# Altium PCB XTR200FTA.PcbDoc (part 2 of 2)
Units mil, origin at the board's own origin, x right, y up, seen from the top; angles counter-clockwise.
Board outline 3639.76 x 1623.7 mil, 4 copper layers (Top Layer, Layer 1, Layer 2, Bottom Layer), stack 53.912 mil thick; 93 components, 52 nets, 249 pads, 61 vias.
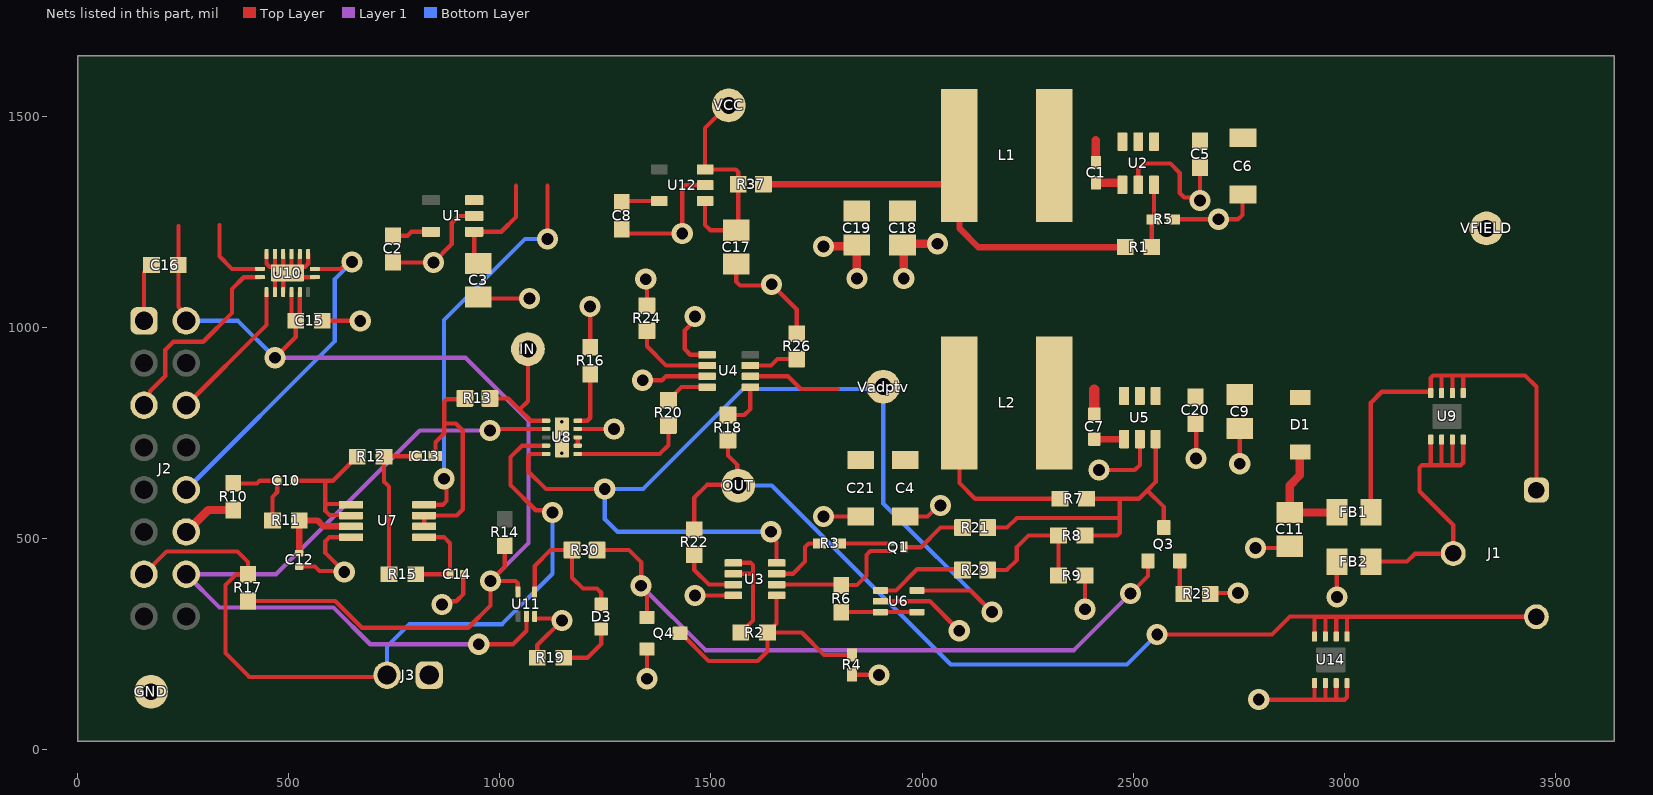
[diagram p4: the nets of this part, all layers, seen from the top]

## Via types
v1: diameter 50, hole 28, Top Layer to Bottom Layer, tented both sides, 48 vias
v2: diameter 19.68, hole 7.87, Top Layer to Bottom Layer, tented both sides, 13 vias

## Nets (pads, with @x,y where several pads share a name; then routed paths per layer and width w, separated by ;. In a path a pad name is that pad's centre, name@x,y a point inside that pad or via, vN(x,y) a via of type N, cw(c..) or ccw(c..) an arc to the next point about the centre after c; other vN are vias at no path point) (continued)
GND: C2.1 C3.1 C4.1 C5.2 C6.2 C8.1 C9.2 C11.2 C12.1 C14.1 C15.2 C16.2 C17.1 C18.2 C19.2 C20.2 C21.1 FB2.1 GND.1 J2.1 J3.1 Q4.2 R4.1 R5.1 R9.1 R16.1 R19.2 R23.1 R24.1 R26.1 U1.2 U2.2 U3.4 U4.1 U4.3 U5.2 U6.2 U7.4 U8.9 U8.11 U10.3 U10.4 U10.8 U10.10 U10.11 U10.12 U10.13 U10.14 U10.15 U10.17 U11.3 U12.2 U14.5 U14.6 U14.7 U14.8 | length 5210.6
  Top Layer w10: J2.1@157.48,1015.35 157.48,1130.52 174.21,1147.25 C16.2@175.2,1147.25 ; U10.15@447.79,1173.85 447.79,1150.68 455.21,1143.26 462.63,1143.26 462.63,1133.42 v2(467.47,1128.58) U10.3@467.47,1083.3 ; U10.17@467.47,1133.42 U10.14@467.47,1173.85 ; U10.4@487.16,1083.3 487.16,1118.73 U10.17@497,1128.58 ; U10.13@487.16,1173.85 487.16,1138.42 U10.17@497,1128.58 ; U10.12@506.84,1173.85 506.84,1138.42 U10.17@497,1128.58 ; C12.1@524.86,433.6 562.44,433.6 573.27,422.77 v1@629.86,422.77 ; U10.17@526.53,1123.58 531.37,1118.73 U10.8@561.96,1118.73 ; U10.17@526.53,1138.42 531.37,1143.26 538.79,1143.26 546.21,1150.68 U10.10@546.21,1173.85 ; U10.17@526.53,1143.26 U10.11@526.53,1173.85 ; C15.2@579.85,1015.35 v1(669.61,1015.35) ; v1(631.69,420.95) v1@629.86,422.77 ; U7.4@647.7,503.05 596.58,503.05 586.94,493.41 586.94,465.69 v1@629.86,422.77 ; C2.1@747.1,1153.99 747.3,1153.79 v1(842.87,1153.79) 886.14,1197.06 886.14,1247.03 902.73,1263.63 U1.2@939.29,1263.63 ; v1(863.29,343.79) 870.94,351.45 896.9,351.45 913.69,368.24 C14.1@913.69,415.35 ; C3.1@949.1,1071.48 952.41,1068.18 v1(1070.17,1068.18) ; U11.3@1082.68,315.35 1082.68,311.63 1083.58,310.73 1142.45,310.73 v1(1147.07,306.1) 1088.58,247.61 R19.2@1088.58,217.52 ; U8.9@1184.48,759.06 v1(1270.34,759.06) ; R16.1@1213.99,952.44 v1(1213.99,1049.35) ; C8.1@1288.59,1232.49 1299.15,1221.94 v1(1432.09,1221.94) 1432.09,1330.76 1437.94,1336.61 U12.2@1486.22,1336.61 ; v1(1338.39,874.76) 1384.19,874.76 1393.43,884 U4.3@1490.96,884 ; v1(1345.6,1113.99) 1348.43,1111.17 R24.1@1348.43,1051.09 ; v1(1348.43,167.91) Q4.2@1348.43,238.19 ; v1(1461.91,365.16) U3.4@1553.15,365.16 ; v1(1461.91,1025.37) 1461.91,1016.73 1437.94,992.76 1437.94,948.43 1451.2,935.18 U4.1@1490.96,935.18 ; C17.1@1559.78,1149.99 1559.78,1108.66 1569.19,1099.25 1641.24,1099.25 v1(1643.85,1101.86) 1703,1042.71 R26.1@1703,984.59 ; v1(1766.24,552.19) C21.1@1854.52,552.19 ; R4.1@1834.02,177 v1(1898.1,177) ; C19.2@1842.13,1191.78 C19.2@1845.76,1188.14 ; U6.2@1901.14,351.18 2018.41,351.18 v1(2088,281.59) ; C18.2@1953.7,1195.08 C18.2@1956.51,1192.28 ; C4.1@1960.65,552.19 2012.79,552.19 2038.68,578.08 v1(2043.46,578.08) ; v1(2385.99,332.29) R9.1@2385.99,412.26 ; v1(2419.04,662.1) 2503.69,662.1 2515.78,674.19 U5.2@2515.78,735.23 ; U2.2@2511.93,1337.36 2511.93,1374.57 2525.15,1387.8 2587.9,1387.8 2610.37,1365.33 2610.37,1318.14 2620.84,1307.67 2650.81,1307.67 v1(2658.46,1300.02) C5.2@2658.46,1378.38 ; R5.1@2594.49,1255.88 v1(2701.69,1255.88) 2748.23,1255.88 2758.54,1266.19 2758.54,1313.33 C6.2@2759.96,1314.75 ; C20.2@2647.42,772 2649.05,770.38 v1(2649.05,689.11) ; R23.1@2682.31,368.66 2684.49,370.85 v1(2748.23,370.85) ; v1(2752.33,676.99) C9.2@2752.33,760.53 ; v1(2789.73,477.36) 2866.93,477.36 C11.2@2871.06,481.49 ; v1(2797.36,118.41) 2797.66,118.11 2929.19,118.11 ; U14.5@2929.49,157.48 2929.49,118.41 2929.19,118.11 ; U14.6@2955.08,157.48 2955.08,118.11 ; U14.7@2980.67,157.48 2980.67,121.04 2977.74,118.11 ; v1(2982.23,361.29) 2982.23,444.73 FB2.1@2982.73,445.23 ; U14.8@3006.26,157.48 3006.26,123.97 3000.4,118.11 2977.74,118.11 ; 2929.19,118.11 2955.08,118.11 ; 2955.08,118.11 2977.74,118.11
  Top Layer w20: v1(1766.94,1191.78) C19.2@1842.13,1191.78 ; v1(1845.76,1115.7) C19.2@1845.76,1188.14 ; v1(1956.51,1115.29) C18.2@1956.51,1192.28 ; C18.2@1956.51,1197.89 v1(2036.29,1197.89)
  other v2: 1147.07,701.97 1147.07,739.37 1147.07,776.77 526.53,1128.58
ID0: J2.5 U10.1 | length 480.9
  Top Layer w10: J2.5@157.48,815.35 157.48,830.23 171.48,844.22 171.48,848.51 207.88,884.91 207.88,946.59 227.26,965.97 297.86,965.97 365.55,1033.66 365.55,1090.6 393.68,1118.73 U10.1@432.04,1118.73
LDO_IN: C17.2 R37.2 U12.1 U12.3 VCC.1 | length 532.5
  Top Layer w10: U12.1@1486.22,1299.21 1486.22,1242.42 1498.66,1229.99 C17.2@1559.78,1229.99 1564.76,1234.98 R37.2@1564.76,1338.58 1564.76,1368.03 1558.78,1374.02 U12.3@1486.22,1374.02 1486.22,1471.64 1540.17,1525.59 VCC.1@1542.14,1525.59
MODE: J2.14 U8.2 U11.2 | length 1916
  Top Layer w10: v1(950.13,249.44) 1031.07,249.44 1062.99,281.36 U11.2@1062.99,315.35 ; v1(976.86,755.51) 980.4,759.06 U8.2@1109.67,759.06
  Layer 1 w10: v1(950.13,249.44) 693.4,249.44 606.22,336.62 336.22,336.62 J2.14@257.48,415.35 470.2,415.35 810.36,755.51 v1(976.86,755.51)
MODE_CTRL: Q3.1 Q4.1 R30.1 | length 1627
  Top Layer w10: R30.1@1230.51,472.44 1306.22,472.44 1334.77,443.9 1334.77,388.26 v1(1334.66,388.15) 1334.66,377.33 1348.43,363.56 Q4.1@1348.43,312.99 Q4.1@1347.07,311.63 ; v1(2493.89,369.7) 2535.24,411.05 Q3.1@2535.17,446.94 Q3.1@2535.17,446.94
  Layer 1 w10: v1@1334.77,388.15 1487.4,235.52 2359.71,235.52 v1(2493.89,369.7)
NetC1_1: C1.1 L1.2 U2.6 | length 53
  Top Layer w20: C1.1@2411.61,1389.76 2411.61,1442.78
NetC1_2: C1.2 U2.1 | length 67
  Top Layer w20: C1.2@2411.61,1342.52 2472.72,1342.52 2474.53,1340.71 U2.1@2474.53,1337.36
NetC7_1: C7.1 U5.1 | length 70.2
  Top Layer w15: C7.1@2408.2,735.16 C7.1@2408.2,735.16 2478.34,735.19 U5.1@2478.38,735.23
NetC7_2: C7.2 L2.2 U5.6 | length 57.8
  Top Layer w25: C7.2@2408.2,794.21 2408.2,852.01
NetC10_1: C10.1 R10.2 R11.1 | length 206.3
  Top Layer w10: R10.2@369.01,630.45 425.02,630.45 431.38,636.81 C10.1@473.68,636.81 472.78,635.91 472.78,609.41 461.87,598.51 R11.1@461.87,542.72
NetC10_2: C10.2 R12.2 U7.1 U7.2 | length 371.6
  Top Layer w10: C10.2@513.05,636.81 586.94,636.81 ; U7.2@647.7,554.23 646.42,555.51 596.58,555.51 586.94,565.15 586.94,581.36 ; U7.1@647.7,579.82 646.16,581.36 586.94,581.36 ; R12.2@662.83,693.49 661.84,693.49 605.17,636.81 586.94,636.81 ; 586.94,581.36 586.94,636.81
NetC11_1: C11.1 D1.2 FB1.1 | length 265.1
  Top Layer w20: D1.2@2895.73,704.58 2894.23,703.08 2894.23,649.17 2871.06,626.01 C11.1@2871.06,561.49 2982.44,561.49 FB1.1@2982.73,561.77
NetC12_2: C12.2 R11.2 U7.3 | length 206.3
  Top Layer w15: C12.2@524.86,465.1 R11.2@524.86,542.72 568.28,542.72 582.35,528.64 U7.3@647.7,528.64
NetC13_1: C13.1 R13.2 U7.6 U7.7 | length 550.3
  Top Layer w10: U7.6@820.92,528.64 U7.7@820.92,554.23 897.94,554.23 912.21,568.5 912.21,755.51 895.73,772 868.45,772 ; C13.1@847.45,694.88 847.45,727.7 868.45,748.7 868.45,772 ; R13.2@917.41,831.75 915.44,829.78 874.31,829.78 868.45,823.93 868.45,772
NetC13_2: C13.2 R12.1 R15.1 | length 358
  Top Layer w10: R15.1@737.71,415.35 737.71,622.66 725.82,634.55 R12.1@725.82,693.49 727.21,694.88 C13.2@800.21,694.88
NetC14_2: C14.2 R15.2 U7.5 | length 222.1
  Top Layer w10: R15.2@800.7,415.35 C14.2@882.2,415.35 882.2,488.75 867.9,503.05 U7.5@820.92,503.05
NetC18_1: C18.1 C19.1 L1.1 R1.2 R37.1 | length 1096.1
  Top Layer w15: R37.1@1624.21,1338.58 2052.75,1338.58 2088.55,1374.39 L1.1@2088.55,1407.48 2088.55,1234.67 2133.23,1189.99 R1.2@2481.09,1189.99
NetD3_1: D3.1 R19.1 | length 137.2
  Top Layer w10: R19.1@1151.57,217.52 1207.3,217.52 1240.16,250.38 D3.1@1240.16,285.43
NetD3_2: D3.2 R30.2 U11.4 | length 338.6
  Top Layer w10: U11.4@1082.68,373.62 1082.68,435.04 1120.08,472.44 1165.87,472.44 1171.06,467.24 1171.06,406.92 1196.77,381.22 1230.51,381.22 1240.16,371.57 D3.2@1240.16,344.49
NetFB1_2: FB1.2 J1.1 U9.1 U9.2 U9.3 U9.4 | length 1084.7
  Top Layer w10: FB1.2@3062.73,561.77 3062.73,821.36 3088.73,847.36 3203.61,847.36 3204.71,846.26 U9.4@3204.71,844.41 3204.71,880.26 3210.57,886.12 3230.3,886.12 ; U9.3@3230.3,844.41 3230.3,886.12 ; U9.2@3255.89,844.41 3255.89,886.12 ; U9.1@3281.48,844.41 3281.48,884.15 3279.52,886.12 ; J1.1@3454.72,614.57 3454.72,859.18 3427.78,886.12 3279.52,886.12 ; 3230.3,886.12 3255.89,886.12 ; 3255.89,886.12 3279.52,886.12
NetFB2_2: FB2.2 J1.2 U9.5 U9.6 U9.7 U9.8 | length 785.1
  Top Layer w10: FB2.2@3062.73,445.23 3148.61,445.23 3167.31,463.93 3257.24,463.93 J1.2@3257.87,464.57 3257.87,532.18 3178.14,611.91 3178.14,667.7 3183.99,673.55 3202.74,673.55 ; U9.5@3204.71,734.17 3204.71,675.52 3202.74,673.55 ; U9.6@3230.3,734.17 3230.3,673.55 ; U9.7@3255.89,734.17 3255.89,674.06 3256.4,673.55 ; U9.8@3281.48,734.17 3281.48,679.41 3275.63,673.55 3256.4,673.55 ; 3202.74,673.55 3230.3,673.55 ; 3230.3,673.55 3256.4,673.55
NetQ1_1: Q1.1 R3.2 | length 122.4
  Top Layer w10: R3.2@1804.54,488.23 Q1.1@1926.89,488.23
NetQ1_2: Q1.2 R6.2 U3.6 | length 337.9
  Top Layer w10: U3.6@1655.51,390.75 1806.54,390.75 R6.2@1808.71,388.58 1809.89,389.76 1846.01,389.76 1868.14,411.89 1868.14,461.16 1877.45,470.47 Q1.2@1929.76,470.47
NetQ1_3: Q1.3 R21.1 | length 157.9
  Top Layer w10: Q1.3@1957.32,479.33 1997.16,479.33 2043.51,525.68 R21.1@2096.03,525.68
NetQ3_2: Q3.2 R23.2 | length 82.1
  Top Layer w10: Q3.2@2609.97,446.94 2609.97,378 R23.2@2619.32,368.66
NetQ4_3: Q4.3 R2.2 R4.2 U3.5 | length 606.1
  Top Layer w10: Q4.3@1427.17,275.59 1429.13,275.59 1494.65,210.08 1611.02,210.08 1633.86,232.92 R2.2@1633.86,277.11 1715.14,277.11 1768.01,224.25 R4.2@1834.02,224.25 ; R2.2@1634.84,277.11 1648.54,290.81 1648.54,291.79 1655.51,298.76 U3.5@1655.51,365.16
NetR1_1: R1.1 R5.2 U2.3 | length 149.5
  Top Layer w10: R1.1@2544.09,1189.99 2544.09,1252.72 2549.33,1257.97 U2.3@2549.33,1337.36
NetR2_1: R2.1 U3.1 U3.2 | length 268.2
  Top Layer w10: U3.2@1553.15,416.34 1599.78,416.34 ; U3.1@1553.15,441.93 1553.84,442.62 1593.92,442.62 1599.78,436.76 1599.78,416.34 ; R2.1@1570.87,277.11 1571.85,277.11 1585.55,290.81 1585.55,291.79 1599.78,306.02 1599.78,416.34
NetR3_1: R3.1 U3.7 | length 151.6
  Top Layer w10: U3.7@1655.51,416.34 1694.06,416.34 1722.96,445.25 1722.96,479.49 1731.7,488.23 R3.1@1757.29,488.23
NetR6_1: R6.1 U6.3 U6.4 | length 179.1
  Top Layer w10: R6.1@1808.71,325.59 U6.3@1901.14,325.59 U6.4@1987.76,325.59
NetR8_1: R8.1 R9.2 R29.2 | length 313.7
  Top Layer w10: R29.2@2155.48,425.29 2200.39,425.29 2224.41,449.31 2224.41,479.46 2251.87,506.93 R8.1@2323,506.93 R9.2@2323,412.26
NetR16_2: R16.2 U8.10 | length 136.5
  Top Layer w10: U8.10@1184.48,778.74 1207.24,778.74 1214.33,785.83 1214.33,889.12 R16.2@1213.99,889.45
NetR18_2: R18.2 U4.5 | length 111.1
  Top Layer w10: R18.2@1540.17,792.35 1578.77,792.35 1578.96,792.15 1593.32,806.52 U4.5@1593.32,858.41
NetR20_1: R20.1 U4.4 | length 104.6
  Top Layer w10: R20.1@1399.27,827.27 1430.41,858.41 U4.4@1490.96,858.41
NetR20_2: R20.2 U8.6 | length 270.5
  Top Layer w10: U8.6@1184.48,700 1378.6,700 1399.27,720.67 R20.2@1399.27,767.82
NetR22_1: R22.1 U3.3 | length 142.8
  Top Layer w10: R22.1@1460.63,461.31 1460.63,425.29 1495.17,390.75 U3.3@1553.15,390.75
NetR24_2: R24.2 U4.2 | length 197.9
  Top Layer w10: R24.2@1348.43,991.64 1348.43,955.14 1393.98,909.59 U4.2@1490.96,909.59
NetR26_2: R26.2 U4.7 | length 116.1
  Top Layer w10: U4.7@1593.32,909.59 1642.35,909.59 1657.91,925.14 R26.2@1703,925.14
NetR29_1: R29.1 U6.1 | length 216.6
  Top Layer w10: U6.1@1901.14,376.77 1938.19,376.77 1988.68,427.25 2094.06,427.25 R29.1@2096.03,425.29
NetU8_7: U8.7 U8.8 | length 19.7
  Top Layer w10: U8.7@1184.48,719.69 U8.8@1184.48,739.37
OD: J2.13 J3.2 R17.1 U8.4 | length 1904.7
  Top Layer w10: J2.13@157.48,415.35 211.16,469.03 379.04,469.03 403.5,444.57 R17.1@403.5,415.04 375.59,415.04 350.31,389.76 350.31,228.81 406.89,172.23 728.97,172.23 J3.2@732.99,176.25 ; U8.4@1109.67,719.69 1052.36,719.69 1025.59,692.91 1025.59,626.23 1085.15,566.66 1119.91,566.66 v1(1125.15,561.42)
  Bottom Layer w10: J3.2@732.99,176.25 732.99,243.85 786.24,297.1 1005.68,297.1 1125.15,416.57 v1(1125.15,561.42)
OUT: J1.3 OUT.1 R18.1 R22.2 U14.1 U14.2 U14.3 U14.4 | length 2610.4
  Top Layer w10: R22.2@1460.63,520.76 1460.63,596.66 1490.96,627 OUT.1@1562.54,627 ; R18.1@1540.17,732.9 1540.17,696.61 1562.54,674.25 OUT.1@1562.54,627 ; OUT.1@1564.42,625.11 OUT.1@1562.54,627 ; v1(2556.74,272.5) 2828.64,272.5 2871.06,314.93 2927.52,314.93 ; U14.4@2929.49,267.72 2929.49,312.96 2927.52,314.93 ; U14.3@2955.08,267.72 2955.08,314.76 ; U14.2@2980.67,267.72 2980.67,314.76 ; U14.1@3006.26,267.72 3006.26,314.76 ; J1.3@3454.72,314.57 3454.53,314.76 3006.26,314.76 ; 2927.52,314.93 2935.23,314.93 2935.39,314.76 2955.08,314.76 ; 2955.08,314.76 2980.67,314.76 ; 2980.67,314.76 3006.26,314.76
  Bottom Layer w10: OUT.1@1564.42,625.11 1644.04,625.11 2067.79,201.36 2485.59,201.36 v1(2556.74,272.5)
PWM_Input: J2.12 R10.1 | length 133.1
  Top Layer w20: J2.12@257.48,515.35 309.59,567.46 R10.1@369.01,567.46
SCLK: J2.6 U10.2 | length 346.8
  Top Layer w10: J2.6@257.48,815.35 447.79,1005.66 U10.2@447.79,1083.3
SDO: J2.10 U10.9 | length 796.4
  Top Layer w10: U10.9@561.96,1138.42 622.51,1138.42 638.88,1154.79 v1(649.7,1154.79)
  Bottom Layer w10: J2.10@257.48,615.35 609.37,967.25 609.37,1114.46 v1(649.7,1154.79)
Vbuck_out: C4.2 C21.2 L2.1 R7.2 U3.8 U4.6 U6.5 U8.5 Vadptv.1 | length 3201.8
  Top Layer w10: U8.5@1109.67,700 1073.28,700 1067.42,694.14 1067.42,658.59 1109.12,616.89 v1(1248.69,616.89) ; U4.6@1593.32,884 1682.24,884 1712.6,853.64 1800.55,853.64 ; v1(1642.35,515.84) 1642.35,505.01 1655.51,491.86 U3.8@1655.51,441.93 ; U6.5@1987.76,376.77 2114.17,376.77 v1(2165.35,325.59) ; L2.1@2088.55,929.32 L2.1@2088.55,821.05 2088.55,631.13 2125.75,593.93 R7.2@2326.52,593.93
  Bottom Layer w10: v1(1642.35,515.84) 1278.52,515.84 1248.69,545.67 v1(1248.69,616.89) 1339.56,616.89 1576.31,853.64 1908.15,853.64 1908.15,582.79 v1(2165.35,325.59) ; Vadptv.1@1908.15,859.46 Vadptv.1@1911.06,856.55
VDD-3V3: C2.2 C15.1 C16.1 J2.2 R14.2 R17.2 U1.5 U10.5 U10.6 U10.16 U11.5 | length 2936.2
  Top Layer w10: C16.1@238.19,1147.25 239.17,1148.23 239.17,1240.16 ; C16.1@239.17,1147.25 239.17,1048.53 J2.2@257.48,1030.23 ; 336.22,1242.34 336.22,1168.34 366.14,1138.42 U10.16@432.04,1138.42 ; R17.2@403.5,352.05 610.46,352.05 674.01,288.51 925.25,288.51 978.18,341.44 v1(978.18,399.1) ; v1(467.47,927.95) 516.85,977.33 C15.1@516.85,1015.35 ; U10.5@506.84,1083.3 506.84,1025.37 C15.1@516.85,1015.35 ; U10.6@526.53,1083.3 526.53,1025.03 C15.1@516.85,1015.35 ; C2.2@747.1,1216.98 781.64,1216.98 790.89,1226.23 U1.5@836.92,1226.23 ; R14.2@1011.86,482.68 1011.86,432.79 v1(978.18,399.1) ; U11.5@1043.31,373.62 1042.4,374.53 1042.4,394.13 1037.43,399.1 v1(978.18,399.1)
  Layer 1 w10: v1(467.47,927.95) 918.66,927.95 1067.91,778.7 1067.91,488.84 v1(978.18,399.1)
  Bottom Layer w10: J2.2@257.48,1015.35 380.07,1015.35 v1(467.47,927.95)
VDD-5V: C3.2 C8.2 U1.1 U1.3 U7.8 U12.5 | length 1304.3
  Top Layer w10: U7.8@820.92,579.82 865.14,579.82 874.12,588.8 874.12,635.22 v1(867.9,641.44) ; C3.2@949.1,1151.48 939.29,1161.3 U1.1@939.29,1226.23 1003.34,1226.23 1038.68,1261.56 1038.68,1335.18 ; v1(1112.95,1209.01) 1112.95,1335.18 ; C8.2@1282.68,1301.39 C8.2@1288.59,1295.49 1292.32,1299.21 U12.5@1377.95,1299.21
  Bottom Layer w10: v1(867.9,641.44) 867.9,1017.17 1059.74,1209.01 v1(1112.95,1209.01)
Vfb: Q3.3 R7.1 R8.2 R21.2 U5.3 | length 874
  Top Layer w10: R21.2@2155.48,525.68 2201.45,525.68 2224.41,548.64 2468.18,548.64 ; R8.2@2385.99,506.93 2462.32,506.93 2468.18,512.79 2468.18,548.64 ; R7.1@2389.51,593.93 2468.18,593.93 ; U5.3@2553.19,735.23 2553.19,633.55 2533.37,613.74 ; Q3.3@2572.57,525.68 2572.57,574.54 2533.37,613.74 ; 2468.18,548.64 2468.18,593.93 ; 2468.18,593.93 2513.56,593.93 2533.37,613.74
Vfield: C5.1 C6.1 C9.1 C20.1 D1.1 U2.4 U2.5 U5.4 U5.5 VFIELD.1
XTR_IN: IN.1 R13.1 U8.1 | length 306.1
  Top Layer w10: R13.1@976.86,831.75 1020.57,831.75 1047.07,805.25 ; IN.1@1066.69,948.43 1066.69,824.86 1047.07,805.25 ; U8.1@1109.67,778.74 1073.58,778.74 1047.07,805.25
pads on no net: J2.3 J2.4 J2.7 J2.8 J2.9 J2.11 J2.15 LBL1.0 U1.4 U4.8 U9.9 U10.7 U11.1 U12.4 U14.9
copper on no net:
  other v2: 2967.87,192.91 2943.27,212.6 2992.48,212.6 2967.87,232.28 3243.1,769.6 3218.49,789.29 3267.7,789.29 3243.1,808.97

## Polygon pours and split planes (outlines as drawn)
NetC18_1 on Top Layer "TOP_LAYER_NETC18_1_P005" (solid, pour order 5): 1787.59,1564.95 1787.59,1249.95 2131.23,1249.95 2131.23,1564.95
Vfield on Top Layer "TOP_LAYER_VFIELD_P017" (solid, pour order 17): 2503.58,1088.85 2503.58,815.67 2949.36,815.67 2955.26,821.57 2955.26,1088.85
VDD-3V3 on Top Layer "TOP_LAYER_VDD-3V3_P016" (solid, pour order 16): 767.11,1200.69 765.8,1202.01 765.8,1643.7 25.54,1643.7 25.54,1198.82
VDD-5V on Top Layer "TOP_LAYER_VDD-5V_P015" (solid, pour order 15): 1307.29,1290.11 918.61,1290.11 918.61,1643.7 1307.29,1643.7
Vbuck_out on Top Layer "TOP_LAYER_VBUCK_OUT_P011" (solid, pour order 11): 2133.57,978.58 2133.51,978.52 1787.59,978.52 1787.59,663.58 2133.43,663.58
Vfield on Top Layer "TOP_LAYER_VFIELD_P010" (solid, pour order 10): 2503.58,918.81 2503.58,1088.85 3639.75,1088.85 3639.75,917.62 2504.77,917.62
Vfield on Top Layer "TOP_LAYER_VFIELD_P013" (solid, pour order 13): 2952.76,1566.62 2952.76,917.62 3639.75,917.62 3639.75,1565.97
NetC7_2 on Top Layer "TOP_LAYER_NETC7_2_P012" (solid, pour order 12): 2489.76,813.65 2489.76,978.52 2301.97,978.52 2301.97,814.97
Vfield on Top Layer "TOP_LAYER_VFIELD_P009" (solid, pour order 9): 2503.58,1422.99 2503.58,1566.29 3639.75,1566.29 3639.75,1422.99
NetC1_1 on Top Layer "TOP_LAYER_NETC1_1_P008" (solid, pour order 8): 2486.22,1419.29 2486.22,1564.95 2268.09,1564.95 2268.09,1419.29
GND on Layer 2 "LAYER_2_GND_P000" (solid, pour order 0): -0.01,1643.7 -0.01,1407.11 -0.01,20 3639.75,20 3639.75,1643.7

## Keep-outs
Keep-Out Layer:
  text ".Layer_Name" at 577,-858.49 h60

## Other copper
Top Layer:
  text ".Layer_Name" at 577,-858.49 h60
Bottom Layer:
  text ".Layer_Name" at 577,-858.49 h60

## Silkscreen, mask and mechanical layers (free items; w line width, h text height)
Top Overlay:
  text "FT-EVP-XTR200-A" at 98.43,1482.28 h108.27
  text ".Layer_Name" at 577,-858.49 h23.62
Bottom Overlay:
  text ".Layer_Name" at 577,-858.49 h60
Top Paste:
  text ".Layer_Name" at 577,-858.49 h60
Bottom Paste:
  text ".Layer_Name" at 577,-858.49 h60
Top Solder:
  text ".Layer_Name" at 577,-858.49 h60
  text ".Layer_Name" at 577,-858.49 h60
Bottom Solder:
  text ".Layer_Name" at 577,-858.49 h60
Drill Guide:
  text ".Layer_Name" at 577,-858.49 h60
M1 Board Outline:
  lines w10: -0.01,20 0,1643.7 3641.91,1643.7 3641.54,19.7 -0.01,20
  text ".Layer_Name" at 577,-858.49 h60
M2 Board Dimensions:
  rectangle: 0,-275 125,-150
  rectangle: 125,-400 500,-275
  lines w7: 0,-275 1000,-275 ; 125,-400 125,-150 ; 250,-400 250,-150 ; 500,-400 500,-150 ; 750,-400 750,-150 ; 0,-400 1000,-400 1000,-150 0,-150 0,-400
  text ".Layer_Name" at 577,-858.49 h60
M3 3D STEP Top:
  text ".Layer_Name" at 577,-858.49 h60
M4 3D STEP Bottom:
  text ".Layer_Name" at 577,-858.49 h60
M5 Assembly Top:
  lines w10: -292,-930.17 6308,-930.17 ; -292,-726.83 6310,-726.83 ; -292,-523.5 -292,-1133.5 3713,-1133.5 6310,-1133.5 6310,-523.5 -291.5,-523.5 -291.5,-1133.5 1284,-1133.5 ; 2173,-1133.5 2173,-523.5 ; 3440,-726.83 3440,-523.5 ; 4280,-726.83 4280,-523.5 ; 4902,-1140 4902,-937.17
  text "COMPONENTS MARKED 'DNP' SHOULD NOT BE POPULATED." at 1153.5,-318.5 h60
  text "ASSEMBLY VARIANT:" at 1153,-434 h60
  text ".VariantName" at 2189,-434 h60
  text "PCB VIEWED FROM TOP SIDE" at -228.5,-655.67 h60
  text "BOARD #:" at 2248,-655.67 h60
  text ".PRJ_Number" at 2793.5,-655.67 h60
  text "REV:" at 3638,-655.67 h60
  text ".PCB_Rev" at 3929.5,-655.67 h60
  text "SVN REV:" at 4476,-655.67 h60
  text ".VersionControl_RevNumber" at 4982,-655.67 h60
  text "TID #:" at 2248,-859 h60
  text ".TID" at 2793.5,-859 h60
  text "PLOT NAME =" at -228.5,-1064.34 h60
  text ".plot_File_Name" at 577,-1064.34 h60
  text "GENERATED    :" at 2250,-1064.34 h60
  text ".Print_Date" at 3119.5,-1064.34 h60
  text ".Print_Time" at 3848.5,-1064.34 h60
  text "TEXAS INSTRUMENTS" at 5113,-1064.34 h60
M6 Assembly Bottom:
  lines w10: -292.5,-727.33 6309.5,-727.33 ; -290.5,-930.67 6309.5,-930.67 ; 1115.5,-1140.5 1115.5,-937.67 ; 1737.5,-727.33 1737.5,-524 ; 2577.5,-727.33 2577.5,-524 ; 3844.5,-1134 3844.5,-524 ; 4733.5,-1134 6309,-1134 6309,-524 -292.5,-524 -292.5,-1134 2304.5,-1134 6309.5,-1134 6309.5,-524
  text "COMPONENTS MARKED 'DNP' SHOULD NOT BE POPULATED." at 6102,-318 h60
  text ".VariantName" at 5058,-434 h60
  text "ASSEMBLY VARIANT:" at 6097,-434 h60
  text ".VersionControl_RevNumber" at 1035.5,-656.17 h60
  text "SVN REV:" at 1541.5,-656.17 h60
  text ".PCB_Rev" at 2088,-656.17 h60
  text "REV:" at 2379.5,-656.17 h60
  text ".PRJ_Number" at 3224,-656.17 h60
  text "BOARD #:" at 3769.5,-656.17 h60
  text "PCB VIEWED FROM BOTTOM SIDE" at 6246,-656.17 h60
  text ".TID" at 3224,-859.5 h60
  text "TID #:" at 3769.5,-859.5 h60
  text "TEXAS INSTRUMENTS" at 904.5,-1064.84 h60
  text ".Print_Time" at 2169,-1064.84 h60
  text ".Print_Date" at 2898,-1064.84 h60
  text "GENERATED    :" at 3767.5,-1064.84 h60
  text ".plot_File_Name" at 5440.5,-1064.84 h60
  text "PLOT NAME =" at 6246,-1064.84 h60
M9 Title Sheet:
  drawing of 57 lines, arcs and shapes, not listed
  text "1" at 739.84,8036.5 h70
  text "2" at 3235.5,8036.5 h70
  text "3" at 5724.84,8036.5 h70
  text "4" at 8231.51,8036.5 h70
  text "5" at 10730.5,8036.5 h70
  text "6" at 13235.5,8036.5 h70
  text "A" at -416.5,6893.5 h70
  text "A" at 14383.5,6893.5 h70
  text "B" at -416.5,4513.5 h70
  text "B" at 14383.5,4513.5 h70
  text "C" at -416.5,2138.5 h70
  text "C" at 14383.5,2138.5 h70
  text "PROJECT TITLE:" at 11343.5,277.5 h45
  text ".PRJ_Title" at 11393.5,144.17 h70
  text "DESIGNED FOR:" at 11343.5,-23.5 h45
  text ".PRJ_Customer" at 11393.5,-163.5 h70
  text "D" at -416.5,-231.5 h70
  text "D" at 14383.5,-231.5 h70
  text "FILE NAME:" at 11343.5,-323.5 h45
  text ".PCB_File_Name_No_Path" at 11393.5,-443.5 h70
  text "Texas Instruments (TI) and/or its licensors do not warrant the accuracy or completeness of this specification" at 6374,-605.34 h45
  text "ENGINEER:" at 11343.5,-613.5 h45
  text "LAYOUT BY:" at 12848.5,-613.5 h45
  text "or any information contained therein. TI and/or its licensors do not warrant that this design will meet" at 6329.01,-718 h45
  text ".PRJ_Engineer" at 11393.5,-768.49 h70
  text ".PCB_Layout" at 12899,-768.49 h70
  text "the specifications, will be suitable for your application or fit for any particular purpose, or will operate in" at 6329.01,-830.67 h45
  text ".Layer_Name" at 577,-858.49 h60
  text "ALTIUM DESIGNER VERSION:" at 12848.5,-923.5 h45
  text "an implementation. TI and/or its licensors do not warrant that the design is production worthy. You should" at 6329.01,-943.33 h45
  text "completely validate and test your design implementation to confirm the system functionality for your application." at 6374,-1056 h45
  text ".print_Scale" at 11393.5,-1056.83 h70
  text ".Application_BuildNumber" at 12899,-1056.83 h70
  text "1" at 739.84,-1263.5 h70
  text "2" at 3235.5,-1263.5 h70
  text "3" at 5724.84,-1263.5 h70
  text "4" at 8231.51,-1263.5 h70
  text "5" at 10730.5,-1263.5 h70
  text "6" at 13235.5,-1263.5 h70
M10 Fab Notes:
  drawing of 189 lines, arcs and shapes, not listed
  text "DESIGN INFORMATION" at 12382.02,6356.17 h60
  text "MIN. TRACK WIDTH:" at 11737.46,6224.05 h60
  text "8" at 12833.7,6224.05 h60
  text "MIL" at 12988.46,6224.05 h60
  text "7.874" at 12667.32,6102.36 h60
  text "MIN. CLEARANCE:" at 11737.46,6099.92 h60
  text "MIL" at 12988.46,6099.92 h60
  text "MIN. VIA PAD SIZE:" at 11737.46,5975.8 h60
  text "24" at 12803.71,5975.8 h60
  text "MIL" at 12988.46,5975.8 h60
  text "0.05mm (2MIL)" at 12432.46,5845.9 h60
  text "MINIMUM ANNULAR RING" at 11408.23,5837.67 h60
  text "EXTERNAL" at 13140.46,5837.67 h60
  text "PER" at 11608.23,5727.55 h60
  text "IPC-D-275 CLASS 2 LEVEL C" at 11828.23,5727.54 h60
  text "MIL, HOLES" at 13316.46,5627.07 h60
  text "+/-" at 12924,5618.48 h60
  text "+/-" at 13778,5618.48 h60
  text "REGISTRATION TOLERANCES:" at 11408.23,5617.42 h60
  text "METAL" at 12608,5617.42 h60
  text "5" at 13184.2,5617.42 h60
  text "3" at 14017.2,5617.42 h60
  text "MIL" at 14133.46,5617.42 h60
  text "HOLE SIZE TOLERANCE (UNLESS OTHERWISE SPECIFIED):" at 11408.23,5519.1 h60
  text "+/-" at 13778,5516.23 h60
  text "3" at 14017.2,5515.17 h60
  text "MIL" at 14133.46,5515.17 h60
  text "MATERIAL:" at 11333.46,5377.52 h60
  text "FR-4 High Tg" at 12319.9,5249 h60
  text "X" at 12175.46,5241.01 h60
  text "FR-4" at 11754.46,5236.49 h60
  text "OTHER" at 13242.46,5236.49 h60
  text "62 MIL (1.6mm) +/-10%" at 12074.56,5093.46 h60
  text "X" at 11954.46,5091.01 h60
  text "THICKNESS:" at 11408.23,5085.24 h60
  text "OTHER" at 13359.46,5085.24 h60
  text "TOLERANCE:" at 11408.23,4946.92 h60
  text "X" at 12256.46,4946.92 h60
  text "ANSI IPC-6012 TYPE 3 CLASS 2" at 12434.48,4946.92 h60
  text "OTHER +/-" at 12434.46,4802.73 h60
  text "BOW & TWIST:" at 11408.23,4657.54 h60
  text "X" at 12256.46,4657.54 h60
  text "ANSI IPC-6012 TYPE 3 CLASS 2" at 12434.48,4657.54 h60
  text "OTHER +/-" at 12434.46,4510.85 h60
  text "DRILLING:" at 11333.46,4380.23 h60
  text "NC_DRILL FILES" at 13094.46,4275.04 h60
  text "REFERENCE:" at 11408.23,4271.1 h60
  text "X" at 12065.46,4271.01 h60
  text "AS SHOWN" at 12243.46,4271.1 h60
  text "X" at 12966.46,4271.1 h60
  text "OTHER" at 13392.46,4128.85 h60
  text "PTH COPPER THICKNESS:" at 11407.91,4125.32 h60
  text "X" at 12547.14,4125.32 h60
  text "20-30 um" at 12675.14,4125.32 h60
  text "BOARD FINISH:" at 11333.46,3977.73 h60
  text "SILKSCREEN:" at 11488.68,3867.6 h60
  text "X" at 12446.46,3867.6 h60
  text "TOP" at 12563.46,3867.6 h60
  text "X" at 12956.46,3867.6 h60
  text "BOTTOM" at 13074.46,3867.6 h60
  text "SILKSCREEN COLOR:" at 11488.68,3712.41 h60
  text "X" at 12445.46,3712.41 h60
  text "WHITE" at 12563.46,3712.41 h60
  text "OTHER" at 13074.46,3712.41 h60
  text "X" at 12576.46,3568.96 h60
  text "GREEN" at 12694.46,3568.96 h60
  text "OTHER" at 13312.46,3568.96 h60
  text "SOLDER RESIST COLOR:" at 11488.68,3562.1 h60
  text "X" at 12576.46,3414.71 h60
  text "MATTE" at 12694.46,3414.71 h60
  text "SEMI-GLOSS" at 13312,3414.07 h60
  text "IMMERSION GOLD (ENIG)" at 12394.46,3241.94 h60
  text "ENEPIG" at 13732,3234.72 h60
  text "SURFACE FINISH:" at 11333.46,3233.72 h60
  text "X" at 12216.46,3233.72 h60
  text "IMM. TIN/SILVER OR EQUIV" at 11663,3096.4 h60
  text "OTHER" at 13094.46,3092.47 h60
  text "ARRAY/PANEL:" at 11333.46,2937.09 h60
  text "CUT AND TRIM PER M1 BOARD OUTLINE" at 12394.46,2928.87 h60
  text "N.C. ROUTE" at 12394.46,2792.9 h60
  text "X" at 13082.46,2792.9 h60
  text "V. SCORE" at 13260.46,2792.9 h60
  text "CERTIFICATION:" at 11333.46,2663.77 h60
  text "MATERIALS AND WORKMANSHIP FOR ALL PCBS" at 12058.46,2663.77 h60
  text "TO MEET OR EXCEED THE REQUIREMENTS OF:" at 12058.46,2569.71 h60
  text "X" at 11695.97,2441.08 h60
  text "ANSI IPC-A-600F CLASS ->" at 11823.96,2441.08 h60
  text "X" at 13471.97,2441.08 h60
  text "2" at 13581.96,2441.08 h60
  text "1" at 13266.96,2439.58 h60
  text "3" at 13935.96,2439.58 h60
  text "X" at 12507.97,2293.39 h60
  text "RoHS" at 12635.96,2293.39 h60
  text "OTHER" at 13280.36,2293.39 h60
  text "PER ORDER" at 13677.42,2293.39 h60
  text "ALL BOARDS MUST MEET OR EXCEED UL94-V0 REQUIREMENTS." at 11361,2139.57 h60
  text "PCB MUST BEAR THE UL94V-0 UL REGISTERED MATERIAL ID NUMBER" at 11361,2023.5 h60
  text "ADDITIONAL REQUIREMENTS:" at 11333.46,1854.08 h60
  text "MICROSECTION:" at 11408.23,1746.95 h60
  text "YES" at 12313.96,1746.95 h60
  text "REQUIRED" at 13175.46,1602.62 h60
  text "BARE BOARD ELEC. TEST:" at 11408.23,1599.76 h60
  text "NONE" at 12713.96,1599.76 h60
  text "X" at 13057.46,1599.76 h60
  text "PER ORDER" at 13767.46,1599.76 h60
  text "XX MIL VIAS REQUIRE NON-CONDUCTIVE FILL AND PLANARIZE" at 11576.38,1394.82 h59
  text "XX MIL VIAS REQUIRE CONDUCTIVE FILL AND PLANARIZE" at 11584.38,1290.84 h60
  text "OUTER XX MIL TRACES REQUIRE 50 OHM SINGLE-ENDED IMPEDANCE" at 11583.39,1127.46 h58
  text "LAYER 2 & 3 (INNER LAYERS) XX MIL WIDE, XX MIL SPACE / TRACES REQUIRE 100 OHM DIFFERENTIAL IMPEDANCE" at 11575.39,891.74 h60
  text ".Layer_Name" at 577,-858.49 h60
M11 Gerber Information:
  lines w10: -292,-930.17 6308,-930.17 ; -292,-726.83 6310,-726.83 ; -292,-523.5 -292,-1133.5 3713,-1133.5 6310,-1133.5 6310,-523.5 -291.5,-523.5 -291.5,-1133.5 1284,-1133.5 ; 2173,-1133.5 2173,-523.5 ; 3440,-726.83 3440,-523.5 ; 4280,-726.83 4280,-523.5 ; 4902,-1140 4902,-937.17
  text "ALL ARTWORK VIEWED FROM TOP SIDE" at -228.5,-655.67 h60
  text "BOARD #:" at 2248,-655.67 h60
  text ".PRJ_Number" at 2793.5,-655.67 h60
  text "REV:" at 3638,-655.67 h60
  text ".PCB_Rev" at 3929.5,-655.67 h60
  text "SVN REV:" at 4476,-655.67 h60
  text ".VersionControl_RevNumber" at 4982,-655.67 h60
  text "LAYER NAME =" at -228.5,-858.49 h60
  text "TID #:" at 2248,-859 h60
  text ".TID" at 2793.5,-859 h60
  text "PLOT NAME =" at -228.5,-1064.34 h60
  text ".plot_File_Name" at 577,-1064.34 h60
  text "GENERATED    :" at 2250,-1064.34 h60
  text ".Print_Date" at 3119.5,-1064.34 h60
  text ".Print_Time" at 3848.5,-1064.34 h60
  text "TEXAS INSTRUMENTS" at 5113,-1064.34 h60
M12 Stackup:
  drawing of 399 lines, arcs and shapes, not listed
  text "Layer" at 9821.59,7874.94 h60
  text "Name" at 10231.51,7874.94 h60
  text "Material" at 11561.12,7874.94 h60
  text "Thickness" at 12160.97,7874.94 h60
  text "Constant" at 12810.81,7874.94 h60
  text "Board Layer Stack" at 13380.67,7874.94 h60
  text "Top Overlay" at 10231.51,7754.94 h60
  text "Top Solder" at 10231.51,7634.94 h60
  text "SM-001" at 11561.12,7634.94 h60
  text "1.00mil" at 12160.97,7634.94 h60
  text "4" at 12810.81,7634.94 h60
  text "Top Surface Finish" at 10231.51,7514.94 h60
  text "PbSn" at 11561.12,7514.94 h60
  text "0.79mil" at 12160.97,7514.94 h60
  text "1" at 9821.59,7394.94 h60
  text "Top Layer" at 10231.51,7394.94 h60
  text "CF-004" at 11561.12,7394.94 h60
  text "1.38mil" at 12160.97,7394.94 h60
  text "Dielectric 1" at 10231.51,7274.94 h60
  text "PP-017" at 11561.12,7274.94 h60
  text "5.10mil" at 12160.97,7274.94 h60
  text "4.3" at 12810.81,7274.94 h60
  text "Dielectric 3" at 10231.51,7154.94 h60
  text "PP-017" at 11561.12,7154.94 h60
  text "5.10mil" at 12160.97,7154.94 h60
  text "4.3" at 12810.81,7154.94 h60
  text "2" at 9821.59,7034.94 h60
  text "Layer 1" at 10231.51,7034.94 h60
  text "CF-004" at 11561.12,7034.94 h60
  text "1.38mil" at 12160.97,7034.94 h60
  text "Dielectric1" at 10231.51,6914.94 h60
  text "Core-039" at 11561.12,6914.94 h60
  text "28.00mil" at 12160.97,6914.94 h60
  text "4.8" at 12810.81,6914.94 h60
  text "3" at 9821.59,6794.94 h60
  text "Layer 2" at 10231.51,6794.94 h60
  text "CF-004" at 11561.12,6794.94 h60
  text "1.38mil" at 12160.97,6794.94 h60
  text "Dielectric 4" at 10231.51,6674.94 h60
  text "PP-017" at 11561.12,6674.94 h60
  text "5.10mil" at 12160.97,6674.94 h60
  text "4.3" at 12810.81,6674.94 h60
  text "Dielectric 2" at 10231.51,6554.94 h60
  text "PP-017" at 11561.12,6554.94 h60
  text "5.10mil" at 12160.97,6554.94 h60
  text "4.3" at 12810.81,6554.94 h60
  text "4" at 9821.59,6434.94 h60
  text "Bottom Layer" at 10231.51,6434.94 h60
  text "CF-004" at 11561.12,6434.94 h60
  text "1.38mil" at 12160.97,6434.94 h60
  text "Bottom Surface Finish" at 10231.51,6314.94 h60
  text "PbSn" at 11561.12,6314.94 h60
  text "0.79mil" at 12160.97,6314.94 h60
  text "Bottom Solder" at 10231.51,6194.94 h60
  text "SM-001" at 11561.12,6194.94 h60
  text "1.00mil" at 12160.97,6194.94 h60
  text "4" at 12810.81,6194.94 h60
  text "Bottom Overlay" at 10231.51,6074.94 h60
  text ".Layer_Name" at 577,-858.49 h60
M13 Component Bodies Top:
  text ".Layer_Name" at 577,-858.49 h60
M14 Component Bodies Bottom:
  text ".Layer_Name" at 577,-858.49 h60
M15 Courtyards Top:
  text ".Layer_Name" at 577,-858.49 h60
M16 Courtyards Bottom:
  text ".Layer_Name" at 577,-858.49 h60
Drill Drawing:
  circle w10: c5363.72,2793 r27.63
  lines w10: 5336.09,2654.87 5349.9,2654.87 5349.9,2641.06 5377.53,2641.06 5377.53,2654.87 5391.34,2654.87 5391.34,2682.5 5377.53,2682.5 5377.53,2696.31 5349.9,2696.31 5349.9,2682.5 5336.09,2682.5 5336.09,2654.87 ; 5336.09,2944.95 5391.34,2944.95 5363.72,2889.7 5336.09,2944.95 ; 5336.09,3014.02 5391.34,3014.02 5391.34,3069.27 5336.09,3069.27 5336.09,3014.02 ; 5336.09,3138.34 5363.72,3152.15 5391.34,3138.34 5377.53,3165.96 5391.34,3193.59 5363.72,3179.78 5336.09,3193.59 5349.9,3165.96 5336.09,3138.34 ; 5336.09,3276.47 5349.9,3276.47 5363.72,3262.66 5377.53,3276.47 5391.34,3276.47 5377.53,3290.28 5391.34,3304.1 5377.53,3304.1 5363.72,3317.91 5349.9,3304.1 5336.09,3304.1 5349.9,3290.28 5336.09,3276.47
  lines w12: 5286,2603.76 8517.49,2603.76 ; 5286,3349.68 8517.49,3349.68 ; 5623.86,2479.44 5623.86,3474 ; 5955.86,2479.44 5955.86,3474 ; 6592.43,2479.44 6592.43,3474 ; 6851.57,2479.44 6851.57,3474 ; 7226.72,2479.44 7226.72,3474 ; 7951.05,2479.44 7951.05,3474 ; 5286,2479.44 8517.49,2479.44 8517.49,3474 5286,3474 5286,2479.44
  text "Symbol" at 5360.59,3386.98 h72
  text "Quantity" at 5661.16,3386.98 h72
  text "Finished Hole Size" at 5993.16,3386.98 h72
  text "Plated" at 6629.72,3386.98 h72
  text "Hole Type" at 6888.86,3386.98 h72
  text "Drill Layer Pair" at 7264.02,3386.98 h72
  text "Hole Tolerance" at 7988.35,3386.98 h72
  text "13" at 5661.16,3262.66 h60
  text "7.87mil (0.200mm)" at 5993.16,3262.66 h60
  text "PTH" at 6629.72,3262.66 h60
  text "Round" at 6888.86,3262.66 h60
  text "Top Layer - Bottom Layer" at 7264.02,3262.66 h60
  text "48" at 5661.16,3138.34 h60
  text "28.00mil (0.711mm)" at 5993.16,3138.34 h60
  text "PTH" at 6629.72,3138.34 h60
  text "Round" at 6888.86,3138.34 h60
  text "Top Layer - Bottom Layer" at 7264.02,3138.34 h60
  text "3" at 5661.16,3014.02 h60
  text "39.37mil (1.000mm)" at 5993.16,3014.02 h60
  text "PTH" at 6629.72,3014.02 h60
  text "Round" at 6888.86,3014.02 h60
  text "Top Layer - Bottom Layer" at 7264.02,3014.02 h60
  text "6" at 5661.16,2889.7 h60
  text "40.00mil (1.016mm)" at 5993.16,2889.7 h60
  text "PTH" at 6629.72,2889.7 h60
  text "Round" at 6888.86,2889.7 h60
  text "Top Layer - Bottom Layer" at 7264.02,2889.7 h60
  text "16" at 5661.16,2765.38 h60
  text "43.31mil (1.100mm)" at 5993.16,2765.38 h60
  text "PTH" at 6629.72,2765.38 h60
  text "Round" at 6888.86,2765.38 h60
  text "Top Layer - Bottom Layer" at 7264.02,2765.38 h60
  text "+/-5.91mil" at 7988.35,2765.38 h60
  text "2" at 5661.16,2641.06 h60
  text "45.28mil (1.150mm)" at 5993.16,2641.06 h60
  text "PTH" at 6629.72,2641.06 h60
  text "Round" at 6888.86,2641.06 h60
  text "Top Layer - Bottom Layer" at 7264.02,2641.06 h60
  text "88 Total" at 5661.16,2516.74 h60
  text ".Layer_Name" at 577,-858.49 h60
M17 Embedded Cavity:
  text ".Layer_Name" at 577,-858.49 h60
M18 Embedded Assembly:
  text ".Layer_Name" at 577,-858.49 h60
M19 Embedded Keepout:
  text ".Layer_Name" at 577,-858.49 h60

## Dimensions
0,-400 to 1000,-400 on M2 Board Dimensions
-0.01,20 to 0,1643.7 on M2 Board Dimensions
0,0 to 3641.54,19.7 on M2 Board Dimensions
